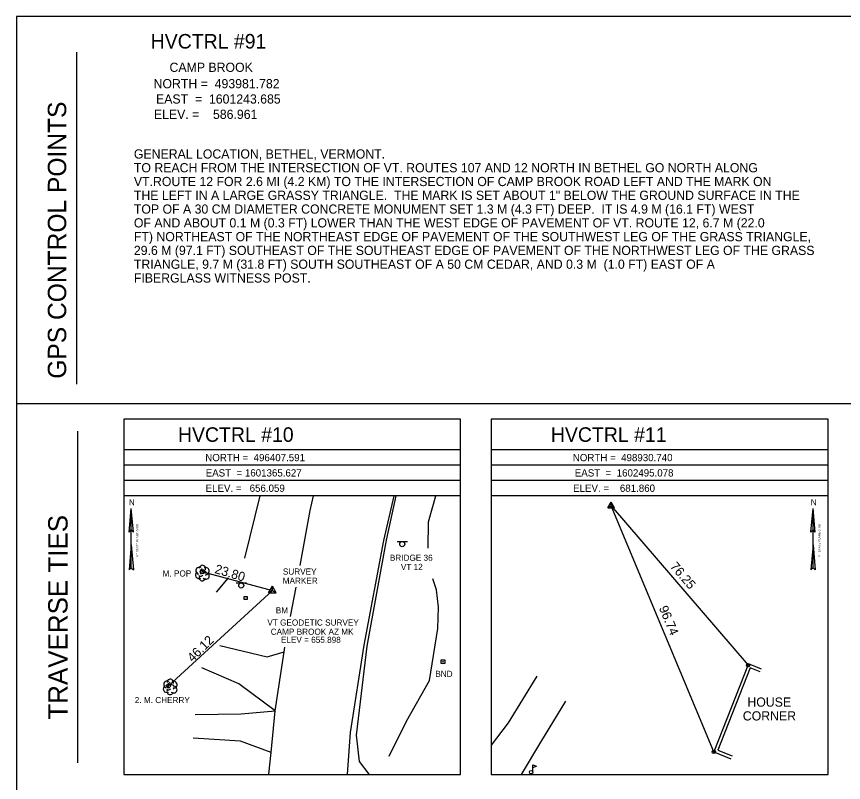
# Model space of a CAD drawing. Extents: x 1598730 to 1599370, y 501440 to 502728.
# Drawn here: x 1598729.5 to 1598999.5, y 502042.9 to 502293 of the extents above; entities that cross this region are included whole.
import ezdxf

# ---------------------------------------------------------------- set-up
doc = ezdxf.new("R2010")
doc.units = 0
for name, color, linetype in [('C_A', 7, 'Continuous'), ('C_C', 7, 'Continuous'), ('CBP', 7, 'Continuous'), ('CPBM', 7, 'Continuous'), ('CPSM', 7, 'Continuous'), ('Default', 7, 'Continuous'), ('L_C', 7, 'Continuous'), ('LAWA', 7, 'Continuous'), ('LBC', 7, 'Continuous'), ('Level 18', 7, 'Continuous'), ('LMB', 7, 'Continuous'), ('LTD', 7, 'Continuous'), ('M_A', 7, 'Continuous'), ('NBL1', 7, 'Continuous'), ('NBL2', 7, 'Continuous'), ('NNA_P', 7, 'Continuous'), ('PET', 7, 'Continuous'), ('PEU', 7, 'Continuous'), ('RDF', 7, 'Continuous'), ('RDW', 7, 'Continuous'), ('RGR', 7, 'Continuous'), ('S_C', 7, 'Continuous'), ('SSGN', 7, 'Continuous')]:
    doc.layers.add(name, color=color, linetype=linetype)

msp = doc.modelspace()

# ---------------------------------------------------------------- linework, layer by layer
at = {"layer": 'CBP'}
for centre, radius in [((1598790.33, 502111.75), 0.625), ((1598790.33, 502111.75), 0.0833), ((1598968.39, 502081.21), 0.562), ((1598968.39, 502081.21), 0.075), ((1598779.14, 502074.45), 0.625), ((1598779.14, 502074.45), 0.0833), ((1598957.19, 502052.9), 0.562), ((1598957.19, 502052.9), 0.075)]:
    msp.add_circle(centre, radius, dxfattribs=at)
at = {"layer": 'CPBM'}
for p, q in [((1598803.86, 502102.65), (1598803.86, 502103.65)), ((1598803.86, 502103.65), (1598804.86, 502103.65)), ((1598804.86, 502102.65), (1598803.86, 502102.65)), ((1598804.36, 502103.15), (1598804.36, 502103.15)), ((1598804.36, 502103.15), (1598804.36, 502103.15)), ((1598804.86, 502103.65), (1598804.86, 502102.65))]:
    msp.add_line(p, q, dxfattribs=at)
at = {"layer": 'CPSM'}
for p, q in [((1598922.56, 502132.59), (1598923.64, 502134.45)), ((1598922.56, 502132.59), (1598923.69, 502133.23)), ((1598922.56, 502132.59), (1598924.81, 502132.59)), ((1598923.69, 502133.23), (1598923.69, 502134.45)), ((1598923.69, 502133.23), (1598924.81, 502132.59)), ((1598923.69, 502133.23), (1598923.69, 502133.23)), ((1598924.81, 502132.59), (1598923.74, 502134.45)), ((1598811.84, 502104.88), (1598813.09, 502107.04)), ((1598811.84, 502104.88), (1598813.09, 502105.6)), ((1598811.84, 502104.88), (1598814.34, 502104.88)), ((1598814.34, 502104.88), (1598813.09, 502107.04)), ((1598813.09, 502105.6), (1598813.09, 502107.04)), ((1598813.09, 502105.6), (1598813.09, 502105.6)), ((1598813.09, 502105.6), (1598814.34, 502104.88))]:
    msp.add_line(p, q, dxfattribs=at)
at = {"layer": 'Default'}
for p, q in [((1598957.19, 502052.9), (1598923.69, 502133.23)), ((1598923.69, 502133.23), (1598968.39, 502081.21))]:
    msp.add_line(p, q, dxfattribs=at)
msp.add_lwpolyline([(1598790.33, 502111.75), (1598813.09, 502105.6), (1598779.14, 502074.45)], dxfattribs=at)
at = {"layer": 'LAWA'}
for points in [[(1598804.08, 502116.13), (1598809.05, 502136.53)], [(1598863.97, 502119.46), (1598864.04, 502127.99), (1598866.43, 502136.53)], [(1598794.85, 502105.04), (1598798.74, 502109.72)], [(1598851.15, 502051.48), (1598856.86, 502062.93), (1598864.41, 502076.27), (1598867.06, 502093.15), (1598867.33, 502100.12), (1598866.69, 502105.82), (1598865.46, 502109.39)]]:
    msp.add_lwpolyline(points, dxfattribs=at)
at = {"layer": 'LBC'}
for p, q in [((1598968.55, 502081.62), (1598957.19, 502052.9)), ((1598972.75, 502079.96), (1598968.55, 502081.62)), ((1598957.19, 502052.9), (1598962.79, 502050.68))]:
    msp.add_line(p, q, dxfattribs=at)
msp.add_lwpolyline([(1598972.39, 502079.03), (1598969.11, 502080.32), (1598958.48, 502053.46), (1598963.16, 502051.61)], dxfattribs=at)
at = {"layer": 'Level 18'}
msp.add_lwpolyline([(1598868.16, 502083.01), (1598869.41, 502083.01), (1598869.41, 502081.76), (1598868.16, 502081.76)], close=True, dxfattribs=at)
msp.add_circle((1598868.78, 502082.39), 0.0833, dxfattribs=at)
at = {"layer": 'LMB'}
for p, q in [((1598898.16, 502048.63), (1598899.32, 502048.28)), ((1598898.16, 502046.29), (1598898.16, 502048.63)), ((1598898.16, 502047.82), (1598899.32, 502048.28)), ((1598897.57, 502046.29), (1598897.57, 502046.29))]:
    msp.add_line(p, q, dxfattribs=at)
msp.add_circle((1598897.57, 502046.29), 0.59, dxfattribs=at)
at = {"layer": 'LTD'}
for p, q in [((1598790.19, 502111.35), (1598790.19, 502111.35)), ((1598790.19, 502111.35), (1598790.19, 502111.35)), ((1598779.68, 502074.2), (1598779.68, 502074.2)), ((1598779.68, 502074.2), (1598779.68, 502074.2))]:
    msp.add_line(p, q, dxfattribs=at)
for centre in [(1598790.23, 502112.78), (1598779.72, 502075.63)]:
    msp.add_arc(centre, 1.05, 335.5272, 180.9563, dxfattribs=at)
for centre, major_axis, ratio, start_param, end_param in [((1598789.4, 502112.01), (1.21, -0.51), 0.895232, 1.570796, 4.712389), ((1598791.23, 502111.93), (-1.14, -0.48), 0.949671, 1.570796, 4.712389), ((1598789.1, 502110.64), (0.58, -1.04), 0.959034, 3.141593, 6.283185), ((1598789.73, 502110.6), (-0.625, -0.083), 0.423636, 0, 3.141593), ((1598789.98, 502111.8), (-0.208, -0.792), 0.645439, 3.141593, 6.283185), ((1598790.69, 502111.18), (-0.5, 0.667), 0.989748, 3.141593, 6.283185), ((1598791.19, 502110.51), (-1.09, 0.79), 0.841452, 1.570796, 4.712389), ((1598790.19, 502109.85), (0.26, 1.06), 0.942809, 1.570796, 4.712389), ((1598778.88, 502074.86), (1.21, -0.51), 0.895232, 1.570796, 4.712389), ((1598779.47, 502074.66), (-0.208, -0.792), 0.645439, 3.141593, 6.283185), ((1598780.72, 502074.78), (-1.14, -0.48), 0.949671, 1.570796, 4.712389), ((1598778.59, 502073.49), (0.58, -1.04), 0.959034, 3.141593, 6.283185), ((1598779.68, 502072.7), (0.26, 1.06), 0.942809, 1.570796, 4.712389), ((1598779.22, 502073.45), (-0.625, -0.083), 0.423636, 0, 3.141593), ((1598780.18, 502074.03), (-0.5, 0.667), 0.989748, 3.141593, 6.283185), ((1598780.68, 502073.37), (-1.09, 0.79), 0.841452, 1.570796, 4.712389)]:
    msp.add_ellipse(centre, major_axis=major_axis, ratio=ratio, start_param=start_param, end_param=end_param, dxfattribs=at)
at = {"layer": 'NBL1'}
msp.add_lwpolyline([(1598729.53, 501873.01), (1599369.53, 501873.01), (1599369.53, 502293.01), (1598729.53, 502293.01)], close=True, dxfattribs=at)
at = {"layer": 'NBL2'}
for p, q in [((1598749.25, 502173), (1598749.25, 502281.34)), ((1598729.53, 502166.68), (1599369.53, 502166.68)), ((1598749.53, 502049.34), (1598749.53, 502157.68)), ((1598874.53, 502151.51), (1598764.53, 502151.51)), ((1598994.53, 502151.51), (1598884.53, 502151.51)), ((1598874.53, 502146.51), (1598764.53, 502146.51)), ((1598994.53, 502146.51), (1598884.53, 502146.51)), ((1598874.53, 502141.51), (1598764.53, 502141.51)), ((1598994.53, 502141.51), (1598884.53, 502141.51)), ((1598874.53, 502136.51), (1598764.53, 502136.51)), ((1598994.53, 502136.51), (1598884.53, 502136.51))]:
    msp.add_line(p, q, dxfattribs=at)
for points in [[(1598764.53, 502045.51), (1598874.53, 502045.51), (1598874.53, 502161.51), (1598764.53, 502161.51)], [(1598884.53, 502045.51), (1598994.53, 502045.51), (1598994.53, 502161.51), (1598884.53, 502161.51)]]:
    msp.add_lwpolyline(points, close=True, dxfattribs=at)
at = {"layer": 'NNA_P'}
for p, q in [((1598766.3, 502124.61), (1598766.99, 502132.4)), ((1598766.99, 502113.03), (1598766.99, 502132.4)), ((1598767.68, 502124.61), (1598766.99, 502132.4)), ((1598988.93, 502124.61), (1598989.62, 502132.4)), ((1598989.63, 502113.03), (1598989.62, 502132.4)), ((1598990.32, 502124.61), (1598989.62, 502132.4)), ((1598766.3, 502124.61), (1598766.99, 502125.37)), ((1598767.69, 502124.61), (1598766.99, 502125.37)), ((1598988.93, 502124.61), (1598989.62, 502125.37)), ((1598990.32, 502124.61), (1598989.62, 502125.37)), ((1598766.99, 502120.55), (1598766.27, 502112.39)), ((1598766.99, 502120.55), (1598767.71, 502112.39)), ((1598989.63, 502120.55), (1598988.91, 502112.39)), ((1598989.62, 502120.55), (1598990.35, 502112.39)), ((1598766.99, 502113.03), (1598766.27, 502112.39)), ((1598766.99, 502113.03), (1598767.71, 502112.39)), ((1598989.63, 502113.03), (1598988.91, 502112.39)), ((1598989.63, 502113.03), (1598990.35, 502112.39))]:
    msp.add_line(p, q, dxfattribs=at)
at = {"layer": 'PET'}
for points in [[(1598822.1, 502113.8), (1598825.41, 502131.69), (1598826.5, 502136.53)], [(1598837.57, 502045.63), (1598838.59, 502059.23), (1598843.06, 502087.71), (1598849.48, 502121.93), (1598852.87, 502136.53)], [(1598819.02, 502097.12), (1598820.79, 502106.68)], [(1598811.86, 502045.63), (1598812.65, 502052.66), (1598813.98, 502066.28), (1598816.89, 502085.63), (1598817.17, 502087.15)]]:
    msp.add_lwpolyline(points, dxfattribs=at)
at = {"layer": 'PEU'}
for points in [[(1598899.39, 502077.64), (1598890.05, 502062.38), (1598884.53, 502055.08)], [(1598894.39, 502045.51), (1598900.77, 502056.12), (1598908.92, 502069.51)]]:
    msp.add_lwpolyline(points, dxfattribs=at)
at = {"layer": 'RDF'}
for points in [[(1598787.87, 502065.09), (1598802.85, 502065.37), (1598813.98, 502066.28)], [(1598812.65, 502052.66), (1598802.62, 502056.4), (1598787.16, 502057.38)]]:
    msp.add_lwpolyline(points, dxfattribs=at)
at = {"layer": 'RDW'}
for points in [[(1598795.86, 502087.63), (1598811.33, 502083.93), (1598816.89, 502085.63)], [(1598813.98, 502066.28), (1598802.09, 502075.09), (1598789.99, 502080.35)]]:
    msp.add_lwpolyline(points, dxfattribs=at)
at = {"layer": 'RGR'}
msp.add_lwpolyline([(1598844.69, 502045.64), (1598841.54, 502049.79), (1598840.5, 502058.37), (1598844.04, 502087.44), (1598850.3, 502122.05), (1598853.52, 502136.53)], dxfattribs=at)
at = {"layer": 'SSGN'}
for p, q in [((1598853.82, 502121.59), (1598857.16, 502121.59)), ((1598855.47, 502120.75), (1598855.47, 502120.75)), ((1598801.27, 502108.07), (1598804.61, 502108.07)), ((1598802.92, 502107.24), (1598802.92, 502107.24))]:
    msp.add_line(p, q, dxfattribs=at)
for centre in [(1598855.47, 502120.75), (1598802.92, 502107.24)]:
    msp.add_circle(centre, 0.833, dxfattribs=at)

# ---------------------------------------------------------------- texts
at = {"layer": 'C_A'}
msp.add_text('BM', height=2, dxfattribs=at).set_placement((1598814.19, 502098.15))
at = {"layer": 'C_C'}
for s, height, p in [('VT GEODETIC SURVEY ', 2, (1598811.42, 502094.15)), ('CAMP BROOK AZ MK', 2, (1598812.53, 502091.15)), ('ELEV = 655.898', 2, (1598815.85, 502088.52)), ('HOUSE', 3, (1598968.17, 502067.67)), ('CORNER', 3, (1598966.67, 502063.17))]:
    msp.add_text(s, height=height, dxfattribs=at).set_placement(p)
at = {"layer": 'Default'}
for s, p in [('GENERAL LOCATION, BETHEL, VERMONT.  ', (1598767.85, 502246.65)), ('TO REACH FROM THE INTERSECTION OF VT. ROUTES 107 AND 12 NORTH IN BETHEL GO NORTH ALONG ', (1598767.85, 502242.15)), ('VT.ROUTE 12 FOR 2.6 MI (4.2 KM) TO THE INTERSECTION OF CAMP BROOK ROAD LEFT AND THE MARK ON ', (1598767.85, 502237.65)), ('THE LEFT IN A LARGE GRASSY TRIANGLE.  THE MARK IS SET ABOUT 1" BELOW THE GROUND SURFACE IN THE ', (1598767.85, 502233.15)), ('TOP OF A 30 CM DIAMETER CONCRETE MONUMENT SET 1.3 M (4.3 FT) DEEP.  IT IS 4.9 M (16.1 FT) WEST ', (1598767.85, 502228.65)), ('OF AND ABOUT 0.1 M (0.3 FT) LOWER THAN THE WEST EDGE OF PAVEMENT OF VT. ROUTE 12, 6.7 M (22.0 ', (1598767.85, 502224.15)), ('FT) NORTHEAST OF THE NORTHEAST EDGE OF PAVEMENT OF THE SOUTHWEST LEG OF THE GRASS TRIANGLE, ', (1598767.85, 502219.65)), ('29.6 M (97.1 FT) SOUTHEAST OF THE SOUTHEAST EDGE OF PAVEMENT OF THE NORTHWEST LEG OF THE GRASS ', (1598767.85, 502215.15)), ('TRIANGLE, 9.7 M (31.8 FT) SOUTH SOUTHEAST OF A 50 CM CEDAR, AND 0.3 M  (1.0 FT) EAST OF A ', (1598767.85, 502210.65)), ('FIBERGLASS WITNESS POST.', (1598767.85, 502206.15))]:
    msp.add_text(s, height=3, dxfattribs=at).set_placement(p)
for s, rotation, p in [('23.80', 343.2297, (1598794.02, 502111.37)), ('76.25', 310.6712, (1598942.75, 502113.35)), ('96.74', 292.6357, (1598939.21, 502099.91)), ('46.12', 44.4354, (1598787.02, 502082.04))]:
    msp.add_text(s, height=3, rotation=rotation, dxfattribs=at).set_placement(p)
at = {"layer": 'L_C'}
for s, p in [('M. POP', (1598777.22, 502110.17)), ('2. M. CHERRY', (1598768.14, 502068.84))]:
    msp.add_text(s, height=2, dxfattribs=at).set_placement(p)
at = {"layer": 'M_A'}
msp.add_text('BND', height=2, dxfattribs=at).set_placement((1598866.27, 502077.39))
at = {"layer": 'NBL2'}
for s, height, p in [('     HVCTRL #91    ', 4.75, (1598764.51, 502282.56)), ('      CAMP BROOK     ', 3, (1598772.8, 502274.94)), ('NORTH =  493981.782 ', 3, (1598774.28, 502269.59)), ('EAST  =  1601243.685', 3, (1598775.08, 502264.59)), ('ELEV. =    586.961  ', 3, (1598774.39, 502259.59)), ('    HVCTRL #10     ', 4.75, (1598775.18, 502154.14)), ('     HVCTRL #11    ', 4.75, (1598895.18, 502154.14)), ('NORTH =  496407.591 ', 2.375, (1598791.15, 502147.82)), ('NORTH =  498930.740 ', 2.375, (1598911.15, 502147.82)), ('EAST  = 1601365.627 ', 2.375, (1598791.3, 502142.82)), ('EAST  =  1602495.078', 2.375, (1598911.81, 502142.82)), ('ELEV. =   656.059   ', 2.375, (1598791.26, 502137.82)), ('ELEV. =    681.860  ', 2.375, (1598911.26, 502137.82))]:
    msp.add_text(s, height=height, dxfattribs=at).set_placement(p)
for s, height, p in [('GPS CONTROL POINTS', 6, (1598745.75, 502174.75)), ('TRAVERSE TIES', 6.3332, (1598746.2, 502063.45))]:
    msp.add_text(s, height=height, rotation=90, dxfattribs=at).set_placement(p)
at = {"layer": 'NNA_P'}
for p in [(1598766.23, 502133.41), (1598988.86, 502133.41)]:
    msp.add_text('N', height=1.97, dxfattribs=at).set_placement(p)
for p in [(1598769.34, 502116.59), (1598991.98, 502116.59)]:
    msp.add_text('VT STATE PLANE GRID', height=0.7, rotation=90.0204, dxfattribs=at).set_placement(p)
at = {"layer": 'S_C'}
for s, p in [('BRIDGE 36 ', (1598851.43, 502115.3)), ('VT 12', (1598855.03, 502112.3)), ('SURVEY ', (1598816.5, 502110.79)), ('MARKER', (1598816.44, 502107.79))]:
    msp.add_text(s, height=2, dxfattribs=at).set_placement(p)

doc.saveas('drawing.dxf')
